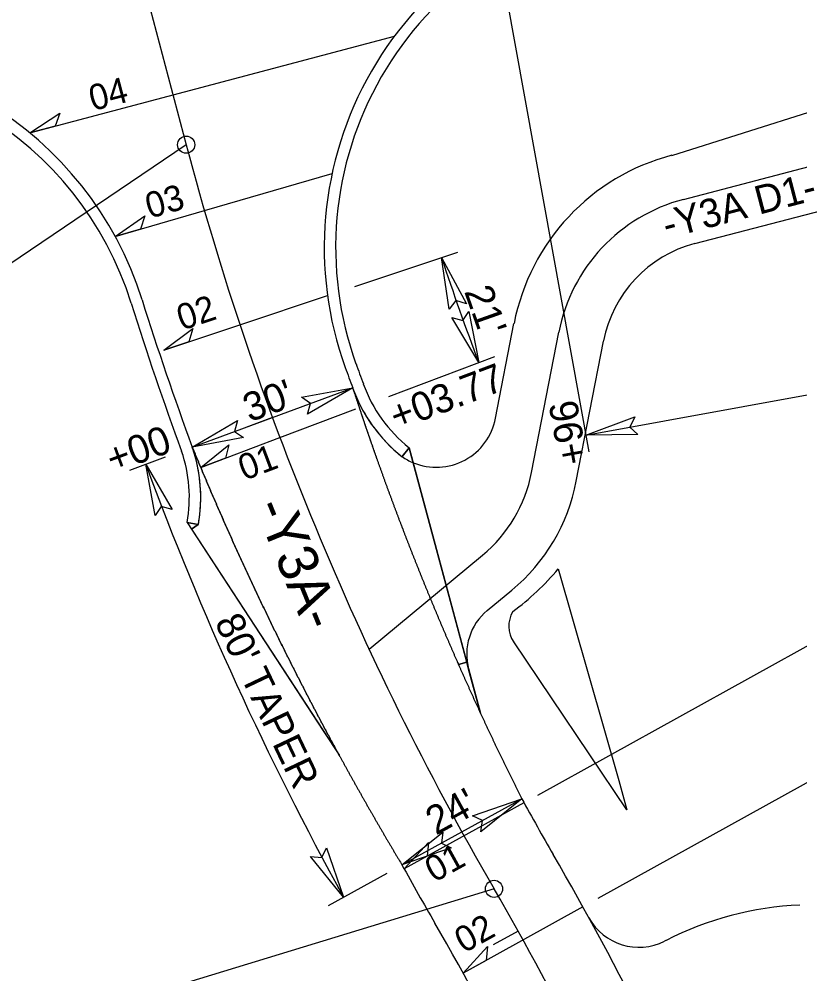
# Model space of a CAD drawing. Extents: x 1616561 to 1622460, y 896726 to 899651.
# Drawn here: x 1620937.7 to 1621074.7, y 897923.3 to 898090.7 of the extents above; entities that cross this region are included whole.
import ezdxf

# ---------------------------------------------------------------- set-up
doc = ezdxf.new("R2010")
doc.units = 0
for name, color, linetype in [('Prop Dimension', 7, 'Continuous'), ('Prop Horizontal Alignment', 7, 'Continuous'), ('Prop Horizontal Alignment Tick Small', 7, 'Continuous'), ('Prop North Arrow NAD83 for Plan Sheets CELL', 7, 'Continuous'), ('Prop Rem of Exist Asph Pvmt', 7, 'Continuous'), ('Prop Shade Light', 7, 'Continuous'), ('Prop Superelevation  Arrow CELL', 7, 'Continuous'), ('Prop Terminator CELL', 7, 'Continuous'), ('Scratch_Level_1', 7, 'Continuous'), ('Sheet Cutting Line CELL', 7, 'Continuous'), ('Sheet North Arrow CELL', 7, 'Continuous'), ('Sheet Sticker Preliminary CELL', 7, 'Continuous')]:
    doc.layers.add(name, color=color, linetype=linetype)

msp = doc.modelspace()

# ---------------------------------------------------------------- linework, layer by layer
at = {"layer": 'Prop Dimension'}
for p, q in [((1621022.41, 898098.88), (1621037.62, 898014.84)), ((1621037.09, 898017.79), (1621184.69, 898044.51)), ((1620968.06, 898015.68), (1620996.21, 898026.07)), ((1620957.08, 898011.62), (1620963.37, 898013.95)), ((1621004.86, 897942.39), (1621025.87, 897953.98)), ((1620991.98, 897935.29), (1621002.23, 897940.95))]:
    msp.add_line(p, q, dxfattribs=at)
msp.add_arc((1621482.13, 898205.52), 556.71, 200.2689, 208.8686, dxfattribs=at)
at = {"layer": 'Prop Horizontal Alignment'}
for p, q in [((1621004.88, 898014), (1621006.12, 898015.57)), ((1621006.12, 898015.57), (1621018.63, 897968.99)), ((1620967.15, 898002.45), (1620993.87, 897961.57)), ((1620967.15, 898002.45), (1620969.12, 898002.1))]:
    msp.add_line(p, q, dxfattribs=at)
for centre, start, end in [((1621021.62, 898035.17), 199.6549, 231.6637), ((1620942.55, 898006.86), 349.8497, 19.0693)]:
    msp.add_arc(centre, 27, start, end, dxfattribs=at)
at = {"layer": 'Prop Horizontal Alignment Tick Small'}
for p, q in [((1621004.88, 898014), (1621006.12, 898015.57)), ((1620969.12, 898002.1), (1620967.15, 898002.45))]:
    msp.add_line(p, q, dxfattribs=at)
for centre, radius, start, end in [((1621053.22, 898050.68), 60, 100.2599, 199.8507), ((1620900.09, 898022.96), 60, 17.4099, 100.1956), ((1621482.13, 898205.52), 550, 197.4143, 200.2689), ((1621482.13, 898205.52), 516, 199.8507, 200.2689), ((1621021.62, 898035.17), 25, 199.6549, 231.6637), ((1620942.55, 898006.86), 25, 349.8497, 18.9734)]:
    msp.add_arc(centre, radius, start, end, dxfattribs=at)
at = {"layer": 'Prop North Arrow NAD83 for Plan Sheets CELL'}
for points in [[(1620939.56, 898070.78), (1620944.84, 898074.25), (1620944.03, 898071.96)], [(1620954.52, 898052.64), (1620959.73, 898056.23), (1620958.96, 898053.93)], [(1620963.08, 898032.69), (1620968.14, 898036.48), (1620967.47, 898034.15)], [(1620969.55, 898012.1), (1620974.46, 898016.09), (1620973.88, 898013.73)], [(1621005.25, 897941.68), (1621009.53, 897946.33), (1621009.3, 897943.92)], [(1621015.61, 897923.4), (1621019.89, 897928.06), (1621019.65, 897925.64)]]:
    msp.add_lwpolyline(points, close=True, dxfattribs=at)
at = {"layer": 'Prop Rem of Exist Asph Pvmt'}
msp.add_line((1621044.32, 897952.03), (1621024.46, 897981.49), dxfattribs=at)
msp.add_lwpolyline([(1621032.28, 897994.31), (1621042.89, 897957.22), (1621044.32, 897952.03)], dxfattribs=at)
for centre, radius, start, end in [((1620995.83, 898025.19), 47.77, 306.567, 319.7364), ((1621028.6, 897984.28), 5, 149.5188, 213.9954)]:
    msp.add_arc(centre, radius, start, end, dxfattribs=at)
at = {"layer": 'Prop Shade Light'}
for p, q in [((1621006.12, 898015.57), (1621004.88, 898014)), ((1621006.82, 898012.94), (1621006.12, 898015.57)), ((1621016.23, 897977.93), (1621006.82, 898012.94)), ((1620969.12, 898002.1), (1620967.15, 898002.45)), ((1620967.15, 898002.45), (1620967.9, 898001.3)), ((1620967.9, 898001.3), (1620969.12, 898002.1)), ((1620969.12, 898002.1), (1620967.9, 898001.3)), ((1620967.9, 898001.3), (1620991.03, 897965.93)), ((1621016.23, 897977.93), (1621014.77, 897977.54)), ((1621014.77, 897977.54), (1621016.23, 897977.93)), ((1620991.03, 897965.93), (1620993.87, 897961.57))]:
    msp.add_line(p, q, dxfattribs=at)
msp.add_lwpolyline([(1621018.63, 897968.99), (1621016.55, 897976.73), (1621016.55, 897976.73), (1621016.23, 897977.93)], dxfattribs=at)
for centre, radius, start, end in [((1621021.62, 898035.17), 27, 199.7084, 207.2565), ((1621021.62, 898035.17), 27, 207.2565, 231.6637), ((1620942.55, 898006.86), 27, 10.9801, 19.052), ((1621010.87, 898022.75), 10.61, 235.595, 247.56), ((1621010.87, 898022.75), 10.61, 235.595, 247.56), ((1620942.55, 898006.86), 27, 349.8497, 10.9801)]:
    msp.add_arc(centre, radius, start, end, dxfattribs=at)
for points in [[(1620996.21, 898026.07), (1620996.37, 898025.57), (1620996.53, 898025.07), (1620996.7, 898024.57), (1620996.86, 898024.07), (1620997.03, 898023.58), (1620997.19, 898023.08), (1620997.33, 898022.66)], [(1620969.55, 898012.1), (1620969.34, 898012.6), (1620969.13, 898013.11), (1620968.91, 898013.62), (1620968.7, 898014.14), (1620968.49, 898014.65), (1620968.27, 898015.17), (1620968.07, 898015.67)], [(1621000.39, 898013.78), (1621000.44, 898013.62), (1621000.62, 898013.13), (1621000.79, 898012.63), (1621000.97, 898012.14), (1621001.15, 898011.64), (1621001.33, 898011.15), (1621001.5, 898010.65), (1621001.68, 898010.16), (1621001.86, 898009.66), (1621002.04, 898009.17), (1621002.22, 898008.67), (1621002.4, 898008.18), (1621002.59, 898007.68), (1621002.77, 898007.19), (1621002.95, 898006.7), (1621003.13, 898006.2), (1621003.32, 898005.71), (1621003.5, 898005.22), (1621003.69, 898004.72), (1621003.87, 898004.23), (1621004.06, 898003.74), (1621004.24, 898003.24), (1621004.43, 898002.75), (1621004.62, 898002.26), (1621004.81, 898001.77), (1621004.87, 898001.59)], [(1620973.43, 898003.08), (1620973.29, 898003.41), (1620973.06, 898003.91), (1620972.84, 898004.42), (1620972.62, 898004.93), (1620972.4, 898005.44), (1620972.17, 898005.95), (1620971.95, 898006.46), (1620971.73, 898006.97), (1620971.51, 898007.48), (1620971.29, 898007.99), (1620971.07, 898008.5), (1620970.86, 898009.01), (1620970.64, 898009.53), (1620970.42, 898010.04), (1620970.2, 898010.55), (1620969.99, 898011.06), (1620969.77, 898011.57), (1620969.56, 898012.09), (1620969.55, 898012.1)], [(1620979.11, 897990.61), (1620979.04, 897990.77), (1620978.8, 897991.27), (1620978.57, 897991.77), (1620978.33, 897992.28), (1620978.1, 897992.78), (1620977.87, 897993.28), (1620977.63, 897993.79), (1620977.4, 897994.29), (1620977.17, 897994.8), (1620976.93, 897995.3), (1620976.7, 897995.8), (1620976.47, 897996.31), (1620976.24, 897996.81), (1620976.01, 897997.32), (1620975.78, 897997.83), (1620975.55, 897998.33), (1620975.32, 897998.84), (1620975.09, 897999.34), (1620974.87, 897999.85), (1620974.64, 898000.36), (1620974.41, 898000.87), (1620974.19, 898001.37), (1620973.96, 898001.88), (1620973.74, 898002.39), (1620973.51, 898002.9), (1620973.43, 898003.08)], [(1621004.87, 898001.59), (1621004.99, 898001.28), (1621005.18, 898000.78), (1621005.37, 898000.29), (1621005.56, 897999.8), (1621005.75, 897999.31), (1621005.94, 897998.82), (1621006.13, 897998.33), (1621006.33, 897997.84), (1621006.52, 897997.35), (1621006.71, 897996.86), (1621006.9, 897996.37), (1621007.1, 897995.88), (1621007.29, 897995.39), (1621007.49, 897994.9), (1621007.68, 897994.41), (1621007.88, 897993.92), (1621008.07, 897993.43), (1621008.27, 897992.94), (1621008.47, 897992.45), (1621008.67, 897991.96), (1621008.86, 897991.47), (1621009.06, 897990.98), (1621009.26, 897990.5), (1621009.46, 897990.01), (1621009.66, 897989.52)], [(1620985.11, 897978.3), (1620984.86, 897978.79), (1620984.61, 897979.29), (1620984.36, 897979.78), (1620984.12, 897980.28), (1620983.87, 897980.78), (1620983.62, 897981.27), (1620983.38, 897981.77), (1620983.13, 897982.27), (1620982.89, 897982.77), (1620982.64, 897983.26), (1620982.4, 897983.76), (1620982.16, 897984.26), (1620981.91, 897984.76), (1620981.67, 897985.26), (1620981.43, 897985.76), (1620981.19, 897986.26), (1620980.95, 897986.76), (1620980.71, 897987.26), (1620980.47, 897987.76), (1620980.23, 897988.26), (1620979.99, 897988.76), (1620979.75, 897989.26), (1620979.51, 897989.77), (1620979.28, 897990.27), (1620979.11, 897990.61)], [(1621009.66, 897989.52), (1621009.86, 897989.03), (1621010.07, 897988.55), (1621010.27, 897988.06), (1621010.47, 897987.57), (1621010.67, 897987.09), (1621010.88, 897986.6), (1621011.08, 897986.11), (1621011.28, 897985.63), (1621011.49, 897985.14), (1621011.69, 897984.65), (1621011.9, 897984.17), (1621012.11, 897983.68), (1621012.31, 897983.2), (1621012.52, 897982.71), (1621012.73, 897982.23), (1621012.94, 897981.74), (1621013.15, 897981.26), (1621013.36, 897980.78), (1621013.57, 897980.29), (1621013.78, 897979.81), (1621013.99, 897979.32), (1621014.2, 897978.84), (1621014.41, 897978.36), (1621014.62, 897977.87), (1621014.77, 897977.54)], [(1620991.39, 897966.16), (1620991.22, 897966.48), (1620990.96, 897966.97), (1620990.7, 897967.46), (1620990.44, 897967.95), (1620990.18, 897968.44), (1620989.93, 897968.93), (1620989.67, 897969.42), (1620989.41, 897969.91), (1620989.15, 897970.4), (1620988.9, 897970.89), (1620988.64, 897971.38), (1620988.38, 897971.88), (1620988.13, 897972.37), (1620987.88, 897972.86), (1620987.62, 897973.35), (1620987.37, 897973.85), (1620987.11, 897974.34), (1620986.86, 897974.83), (1620986.61, 897975.33), (1620986.36, 897975.82), (1620986.11, 897976.31), (1620985.86, 897976.81), (1620985.61, 897977.3), (1620985.36, 897977.8), (1620985.11, 897978.3)], [(1621014.77, 897977.54), (1621014.84, 897977.39), (1621015.05, 897976.91), (1621015.26, 897976.43), (1621015.48, 897975.94), (1621015.69, 897975.46), (1621015.91, 897974.98), (1621016.12, 897974.5), (1621016.34, 897974.02), (1621016.56, 897973.54), (1621016.77, 897973.05), (1621016.99, 897972.57), (1621017.21, 897972.09), (1621017.43, 897971.61), (1621017.65, 897971.13), (1621017.87, 897970.65), (1621018.09, 897970.17), (1621018.31, 897969.69), (1621018.53, 897969.21), (1621018.63, 897968.99)], [(1620993.87, 897961.57), (1620993.85, 897961.6), (1620993.59, 897962.09), (1620993.32, 897962.58), (1620993.06, 897963.06), (1620992.8, 897963.55), (1620992.53, 897964.04), (1620992.27, 897964.53), (1620992.01, 897965.01), (1620991.74, 897965.5), (1620991.48, 897965.99), (1620991.39, 897966.16)]]:
    msp.add_spline(points, degree=3, dxfattribs=at)
msp.add_open_spline([(1620997.33, 898022.66), (1620997.34, 898022.63), (1620997.35, 898022.6), (1620997.36, 898022.58), (1620997.41, 898022.41), (1620997.47, 898022.25), (1620997.53, 898022.08), (1620997.58, 898021.91), (1620997.64, 898021.75), (1620997.69, 898021.58), (1620997.75, 898021.41), (1620997.8, 898021.25), (1620997.86, 898021.08), (1620997.92, 898020.92), (1620997.97, 898020.75), (1620998.03, 898020.58), (1620998.09, 898020.42), (1620998.14, 898020.25), (1620998.2, 898020.09), (1620998.25, 898019.92), (1620998.31, 898019.75), (1620998.37, 898019.59), (1620998.42, 898019.42), (1620998.48, 898019.26), (1620998.54, 898019.09), (1620998.59, 898018.92), (1620998.65, 898018.76), (1620998.71, 898018.59), (1620998.76, 898018.43), (1620998.82, 898018.26), (1620998.88, 898018.09), (1620998.94, 898017.93), (1620998.99, 898017.76), (1620999.05, 898017.6), (1620999.11, 898017.43), (1620999.16, 898017.27), (1620999.22, 898017.1), (1620999.28, 898016.93), (1620999.34, 898016.77), (1620999.39, 898016.6), (1620999.45, 898016.44), (1620999.51, 898016.27), (1620999.57, 898016.11), (1620999.63, 898015.94), (1620999.68, 898015.78), (1620999.74, 898015.61), (1620999.8, 898015.44), (1620999.86, 898015.28), (1620999.91, 898015.11), (1620999.97, 898014.95), (1621000.03, 898014.78), (1621000.09, 898014.62), (1621000.15, 898014.45), (1621000.21, 898014.29), (1621000.26, 898014.12), (1621000.3, 898014.01), (1621000.35, 898013.89), (1621000.39, 898013.78)], degree=3, dxfattribs=at)
at = {"layer": 'Prop Superelevation  Arrow CELL'}
for p, q in [((1620982.13, 898020.88), (1620977.44, 898019.14)), ((1621025.23, 897930.79), (1621020.86, 897928.35))]:
    msp.add_line(p, q, dxfattribs=at)
at = {"layer": 'Prop Terminator CELL'}
for p, q in [((1621052.21, 898066.85), (1621077.33, 898074.8)), ((1621056.25, 898051.37), (1621081.72, 898058.02)), ((1621021.29, 898020.74), (1621024.51, 898037.33)), ((1621035.44, 898009.68), (1621040.22, 898034.28)), ((1621019.83, 897987.02), (1621024.11, 897990.57)), ((1621051.18, 897929.14), (1621050.94, 897929.02))]:
    msp.add_line(p, q, dxfattribs=at)
for points in [[(1621013.16, 898039.88), (1621011.78, 898048.91), (1621016.16, 898040.83), (1621014.28, 898041.41)], [(1621016.59, 898039.47), (1621018.32, 898030.5), (1621013.63, 898038.4), (1621015.53, 898037.89)], [(1620987.23, 898024.41), (1620996.21, 898026.07), (1620988.27, 898021.44), (1620988.79, 898023.34)], [(1620977.04, 898017.34), (1620968.06, 898015.68), (1620976, 898020.32), (1620975.47, 898018.42)], [(1621046.22, 898017.87), (1621037.09, 898017.79), (1621045.71, 898020.98), (1621044.86, 898019.2)], [(1620961.56, 898003.68), (1620959.9, 898012.66), (1620964.53, 898004.73), (1620962.63, 898005.25)], [(1621017.24, 897950.99), (1621025.87, 897953.98), (1621018.72, 897948.21), (1621018.96, 897950.17)], [(1621013.49, 897945.38), (1621004.86, 897942.39), (1621012.01, 897948.16), (1621011.78, 897946.21)], [(1620991.62, 897945.37), (1620994.61, 897936.74), (1620988.83, 897943.89), (1620990.79, 897943.66)]]:
    msp.add_lwpolyline(points, close=True, dxfattribs=at)
for centre, radius, start, end in [((1621053.22, 898050.68), 62, 100.2599, 199.8507), ((1620900.09, 898022.96), 62, 17.4099, 100.1956), ((1621061.82, 898030.09), 38, 104.6458, 169.0019), ((1621061.82, 898030.09), 22, 104.6458, 169.0019), ((1621482.13, 898205.52), 548, 197.4143, 200.2689), ((1621482.13, 898205.52), 518, 199.8507, 200.2689), ((1621010.87, 898022.75), 10.61, 247.56, 349.0648), ((1621003.05, 898015.97), 33, 309.6601, 349.0019), ((1621026.21, 897979.32), 10, 129.6601, 195.0406), ((1621482.13, 898205.52), 521, 208.8686, 210.1014), ((1620559.89, 897670.89), 545, 15.403, 30.1014), ((1621482.13, 898205.52), 545, 208.8686, 210.1014), ((1621077.43, 897877.42), 58, 92.7166, 116.9035), ((1621046.42, 897937.94), 10, 208.7621, 296.9035), ((1620559.89, 897670.89), 521, 15.403, 30.1014)]:
    msp.add_arc(centre, radius, start, end, dxfattribs=at)
for points in [[(1620996.21, 898026.07), (1620996.37, 898025.57), (1620996.53, 898025.07), (1620996.7, 898024.57), (1620996.86, 898024.07), (1620997.03, 898023.58), (1620997.19, 898023.08), (1620997.36, 898022.58), (1620997.53, 898022.08), (1620997.69, 898021.58), (1620997.86, 898021.08), (1620998.03, 898020.58), (1620998.2, 898020.09), (1620998.37, 898019.59), (1620998.54, 898019.09), (1620998.71, 898018.59), (1620998.88, 898018.09), (1620999.05, 898017.6), (1620999.22, 898017.1), (1620999.39, 898016.6), (1620999.57, 898016.11), (1620999.74, 898015.61), (1620999.91, 898015.11), (1621000.09, 898014.62), (1621000.26, 898014.12), (1621000.44, 898013.62), (1621000.62, 898013.13), (1621000.79, 898012.63), (1621000.97, 898012.14), (1621001.15, 898011.64), (1621001.33, 898011.15), (1621001.5, 898010.65), (1621001.68, 898010.16), (1621001.86, 898009.66), (1621002.04, 898009.17), (1621002.22, 898008.67), (1621002.4, 898008.18), (1621002.59, 898007.68), (1621002.77, 898007.19), (1621002.95, 898006.7), (1621003.13, 898006.2), (1621003.32, 898005.71), (1621003.5, 898005.22), (1621003.69, 898004.72), (1621003.87, 898004.23), (1621004.06, 898003.74), (1621004.24, 898003.24), (1621004.43, 898002.75), (1621004.62, 898002.26), (1621004.81, 898001.77), (1621004.99, 898001.28), (1621005.18, 898000.78), (1621005.37, 898000.29), (1621005.56, 897999.8), (1621005.75, 897999.31), (1621005.94, 897998.82), (1621006.13, 897998.33), (1621006.33, 897997.84), (1621006.52, 897997.35), (1621006.71, 897996.86), (1621006.9, 897996.37), (1621007.1, 897995.88), (1621007.29, 897995.39), (1621007.49, 897994.9), (1621007.68, 897994.41), (1621007.88, 897993.92), (1621008.07, 897993.43), (1621008.27, 897992.94), (1621008.47, 897992.45), (1621008.67, 897991.96), (1621008.86, 897991.47), (1621009.06, 897990.98), (1621009.26, 897990.5), (1621009.46, 897990.01), (1621009.66, 897989.52)], [(1620968.06, 898015.68), (1620968.27, 898015.17), (1620968.49, 898014.65), (1620968.7, 898014.14), (1620968.91, 898013.62), (1620969.13, 898013.11), (1620969.34, 898012.6), (1620969.56, 898012.09), (1620969.77, 898011.57), (1620969.99, 898011.06), (1620970.2, 898010.55), (1620970.42, 898010.04), (1620970.64, 898009.53), (1620970.86, 898009.01), (1620971.07, 898008.5), (1620971.29, 898007.99), (1620971.51, 898007.48), (1620971.73, 898006.97), (1620971.95, 898006.46), (1620972.17, 898005.95), (1620972.4, 898005.44), (1620972.62, 898004.93), (1620972.84, 898004.42), (1620973.06, 898003.91), (1620973.29, 898003.41), (1620973.51, 898002.9), (1620973.74, 898002.39), (1620973.96, 898001.88), (1620974.19, 898001.37), (1620974.41, 898000.87), (1620974.64, 898000.36), (1620974.87, 897999.85), (1620975.09, 897999.34), (1620975.32, 897998.84), (1620975.55, 897998.33), (1620975.78, 897997.83), (1620976.01, 897997.32), (1620976.24, 897996.81), (1620976.47, 897996.31), (1620976.7, 897995.8), (1620976.93, 897995.3), (1620977.17, 897994.8), (1620977.4, 897994.29), (1620977.63, 897993.79), (1620977.87, 897993.28), (1620978.1, 897992.78), (1620978.33, 897992.28), (1620978.57, 897991.77), (1620978.8, 897991.27), (1620979.04, 897990.77), (1620979.28, 897990.27), (1620979.51, 897989.77), (1620979.75, 897989.26), (1620979.99, 897988.76), (1620980.23, 897988.26), (1620980.47, 897987.76), (1620980.71, 897987.26), (1620980.95, 897986.76), (1620981.19, 897986.26), (1620981.43, 897985.76), (1620981.67, 897985.26), (1620981.91, 897984.76), (1620982.16, 897984.26), (1620982.4, 897983.76), (1620982.64, 897983.26), (1620982.89, 897982.77), (1620983.13, 897982.27), (1620983.38, 897981.77), (1620983.62, 897981.27), (1620983.87, 897980.78), (1620984.12, 897980.28), (1620984.36, 897979.78), (1620984.61, 897979.29), (1620984.86, 897978.79), (1620985.11, 897978.3)], [(1621009.66, 897989.52), (1621009.86, 897989.03), (1621010.07, 897988.55), (1621010.27, 897988.06), (1621010.47, 897987.57), (1621010.67, 897987.09), (1621010.88, 897986.6), (1621011.08, 897986.11), (1621011.28, 897985.63), (1621011.49, 897985.14), (1621011.69, 897984.65), (1621011.9, 897984.17), (1621012.11, 897983.68), (1621012.31, 897983.2), (1621012.52, 897982.71), (1621012.73, 897982.23), (1621012.94, 897981.74), (1621013.15, 897981.26), (1621013.36, 897980.78), (1621013.57, 897980.29), (1621013.78, 897979.81), (1621013.99, 897979.32), (1621014.2, 897978.84), (1621014.41, 897978.36), (1621014.62, 897977.87), (1621014.84, 897977.39), (1621015.05, 897976.91), (1621015.26, 897976.43), (1621015.48, 897975.94), (1621015.69, 897975.46), (1621015.91, 897974.98), (1621016.12, 897974.5), (1621016.34, 897974.02), (1621016.56, 897973.54), (1621016.77, 897973.05), (1621016.99, 897972.57), (1621017.21, 897972.09), (1621017.43, 897971.61), (1621017.65, 897971.13), (1621017.87, 897970.65), (1621018.09, 897970.17), (1621018.31, 897969.69), (1621018.53, 897969.21), (1621018.75, 897968.73), (1621018.98, 897968.25), (1621019.2, 897967.78), (1621019.42, 897967.3), (1621019.65, 897966.82), (1621019.87, 897966.34), (1621020.09, 897965.86), (1621020.32, 897965.38), (1621020.55, 897964.91), (1621020.77, 897964.43), (1621021, 897963.95), (1621021.23, 897963.48), (1621021.45, 897963), (1621021.68, 897962.52), (1621021.91, 897962.05), (1621022.14, 897961.57), (1621022.37, 897961.09), (1621022.6, 897960.62), (1621022.83, 897960.14), (1621023.06, 897959.67), (1621023.29, 897959.19), (1621023.53, 897958.72), (1621023.76, 897958.24), (1621023.99, 897957.77), (1621024.23, 897957.29), (1621024.46, 897956.82), (1621024.69, 897956.35), (1621024.93, 897955.87), (1621025.16, 897955.4), (1621025.4, 897954.93), (1621025.87, 897953.98)], [(1620985.11, 897978.3), (1620985.36, 897977.8), (1620985.61, 897977.3), (1620985.86, 897976.81), (1620986.11, 897976.31), (1620986.36, 897975.82), (1620986.61, 897975.33), (1620986.86, 897974.83), (1620987.11, 897974.34), (1620987.37, 897973.85), (1620987.62, 897973.35), (1620987.88, 897972.86), (1620988.13, 897972.37), (1620988.38, 897971.88), (1620988.64, 897971.38), (1620988.9, 897970.89), (1620989.15, 897970.4), (1620989.41, 897969.91), (1620989.67, 897969.42), (1620989.93, 897968.93), (1620990.18, 897968.44), (1620990.44, 897967.95), (1620990.7, 897967.46), (1620990.96, 897966.97), (1620991.22, 897966.48), (1620991.48, 897965.99), (1620991.74, 897965.5), (1620992.01, 897965.01), (1620992.27, 897964.53), (1620992.53, 897964.04), (1620992.8, 897963.55), (1620993.06, 897963.06), (1620993.32, 897962.58), (1620993.59, 897962.09), (1620993.85, 897961.6), (1620994.12, 897961.12), (1620994.39, 897960.63), (1620994.65, 897960.15), (1620994.92, 897959.66), (1620995.19, 897959.18), (1620995.45, 897958.69), (1620995.72, 897958.21), (1620995.99, 897957.72), (1620996.26, 897957.24), (1620996.53, 897956.76), (1620996.8, 897956.27), (1620997.07, 897955.79), (1620997.35, 897955.31), (1620997.62, 897954.83), (1620997.89, 897954.34), (1620998.16, 897953.86), (1620998.44, 897953.38), (1620998.71, 897952.9), (1620998.98, 897952.42), (1620999.26, 897951.94), (1620999.54, 897951.46), (1620999.81, 897950.98), (1621000.09, 897950.5), (1621000.36, 897950.02), (1621000.64, 897949.54), (1621000.92, 897949.06), (1621001.2, 897948.58), (1621001.48, 897948.11), (1621001.76, 897947.63), (1621002.03, 897947.15), (1621002.31, 897946.67), (1621002.6, 897946.2), (1621002.88, 897945.72), (1621003.16, 897945.25), (1621003.44, 897944.77), (1621003.72, 897944.29), (1621004.01, 897943.82), (1621004.29, 897943.34), (1621004.86, 897942.39)]]:
    msp.add_spline(points, degree=3, dxfattribs=at)
at = {"layer": 'Sheet Cutting Line CELL'}
for p, q in [((1620954.2, 898116.85), (1620966.99, 898068.72)), ((1621054.23, 898059.11), (1621100.87, 898071.3)), ((1621027.59, 898011.21), (1621032.37, 898035.81)), ((1620999.09, 897980.22), (1621019, 897996.73))]:
    msp.add_line(p, q, dxfattribs=at)
for centre, radius, start, end in [((1621482.13, 898205.52), 533, 194.8727, 210.1014), ((1621061.82, 898030.09), 30, 104.6458, 169.0019), ((1621003.05, 898015.97), 25, 309.6601, 349.0019), ((1620559.89, 897670.89), 533, 15.403, 30.1014)]:
    msp.add_arc(centre, radius, start, end, dxfattribs=at)
at = {"layer": 'Sheet North Arrow CELL'}
for p, q in [((1620966.99, 898068.72), (1620834.98, 897979.47)), ((1621021.01, 897938.2), (1620912.28, 897905.02))]:
    msp.add_line(p, q, dxfattribs=at)
for centre in [(1620966.99, 898068.72), (1621021.01, 897938.2)]:
    msp.add_circle(centre, 1.5, dxfattribs=at)
at = {"layer": 'Sheet Sticker Preliminary CELL'}
for p, q in [((1620939.56, 898070.78), (1621003.54, 898087.77)), ((1620970.19, 898057.18), (1620992.6, 898063.68)), ((1620954.52, 898052.64), (1620970.19, 898057.18)), ((1620996.58, 898043.84), (1621014.63, 898049.85)), ((1620976.43, 898037.13), (1620991.8, 898042.25)), ((1620963.08, 898032.69), (1620976.43, 898037.13)), ((1621002.54, 898024.55), (1621021.13, 898031.56)), ((1620983.45, 898017.34), (1620996.77, 898022.37)), ((1620969.55, 898012.1), (1620983.45, 898017.34)), ((1621028.67, 897954.64), (1621085.45, 897986.05)), ((1621095.81, 897967.84), (1621039.23, 897936.49)), ((1621026.25, 897953.3), (1621005.25, 897941.68)), ((1621036.6, 897935.03), (1621015.61, 897923.4))]:
    msp.add_line(p, q, dxfattribs=at)
msp.add_arc((1621482.13, 898205.52), 495.73, 198.4167, 200.6741, dxfattribs=at)

# ---------------------------------------------------------------- texts
at = {"layer": 'Prop Dimension'}
for s, rotation, p in [("30'", 20.2689, (1620978.12, 898020)), ('+96', 100.2599, (1621037.5, 898013.04)), ('+00', 20.2689, (1620954.13, 898011.02)), ("80' TAPER", 295.4371, (1620971.91, 897985)), ("24'", 28.8686, (1621010.82, 897947.51))]:
    msp.add_text(s, height=5, rotation=rotation, dxfattribs=at).set_placement(p)
at = {"layer": 'Scratch_Level_1'}
msp.add_text('-Y3A D1-', height=5, rotation=14.6458, dxfattribs=at).set_placement((1621051.31, 898052.19))
at = {"layer": 'Sheet North Arrow CELL'}
msp.add_text('-Y3A-', height=7, rotation=292.2439, dxfattribs=at).set_placement((1620978.92, 898005.21))
at = {"layer": 'Sheet Sticker Preliminary CELL'}
for s, height, rotation, p in [('04', 4.5, 14.8727, (1620950.63, 898074.6)), ('03', 4.5, 16.1593, (1620960.6, 898055.72)), ("21'", 5, 289.5293, (1621015.73, 898043)), ('02', 4.5, 18.4167, (1620966.26, 898036.09)), ('+03.77', 5, 20.6741, (1621003.91, 898018.55)), ('01', 4.5, 20.6741, (1620977.19, 898009.76)), ('01', 4.5, 28.9546, (1621010.5, 897939.22)), ('02', 4.5, 28.9908, (1621015.71, 897926.82))]:
    msp.add_text(s, height=height, rotation=rotation, dxfattribs=at).set_placement(p)

doc.saveas('drawing.dxf')
